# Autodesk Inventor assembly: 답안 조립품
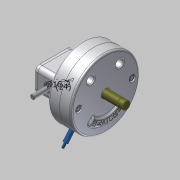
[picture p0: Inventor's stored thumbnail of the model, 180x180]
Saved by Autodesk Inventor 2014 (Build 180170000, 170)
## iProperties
Created: 2015-04
Part Number: 답안 조립품
Document SubType Name: Assembly
Designer: Administrator
Author: Administrator
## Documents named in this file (15)
- C:\Documents and Settings\Administrator\바탕 화면\350406V1025\350406V1025\답안 조립품.iam
- C:\Documents and Settings\Administrator\바탕 화면\350406V1025\350406V1025\본체.ipt
- C:\Documents and Settings\Administrator\바탕 화면\350406V1025\350406V1025\슬라이더3.ipt
- C:\Documents and Settings\Administrator\바탕 화면\350406V1025\350406V1025\부시.ipt
- C:\Documents and Settings\Administrator\바탕 화면\350406V1025\350406V1025\커버2.ipt
- C:\Documents and Settings\Administrator\바탕 화면\350406V1025\350406V1025\M 5 x 12.ipt
- C:\Documents and Settings\Administrator\바탕 화면\350406V1025\350406V1025\축.ipt
- C:\Documents and Settings\Administrator\바탕 화면\350406V1025\350406V1025\멈춤링.ipt
- C:\Documents and Settings\Administrator\바탕 화면\350406V1025\350406V1025\베어링62_22.ipt
- C:\Documents and Settings\Administrator\바탕 화면\350406V1025\350406V1025\슬라이더2.ipt
- C:\Documents and Settings\Administrator\바탕 화면\350406V1025\350406V1025\슬라이더.ipt
- C:\Documents and Settings\Administrator\바탕 화면\350406V1025\350406V1025\평행핀.ipt
- C:\Documents and Settings\Administrator\바탕 화면\350406V1025\350406V1025\커버.ipt
- C:\Documents and Settings\Administrator\바탕 화면\350406V1025\350406V1025\M 10 x 35.ipt
- C:\Documents and Settings\Administrator\바탕 화면\350406V1025\350406V1025\가변스프링..ipt
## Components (6 placed, 4 different names)
1. M 5 x 12:1
2. M 5 x 12:2
3. KS B 1320 B B 5 x  20:1
4. M 10 x 35:1
5. M 10 x 35:2
6. 가변스프링.:1
